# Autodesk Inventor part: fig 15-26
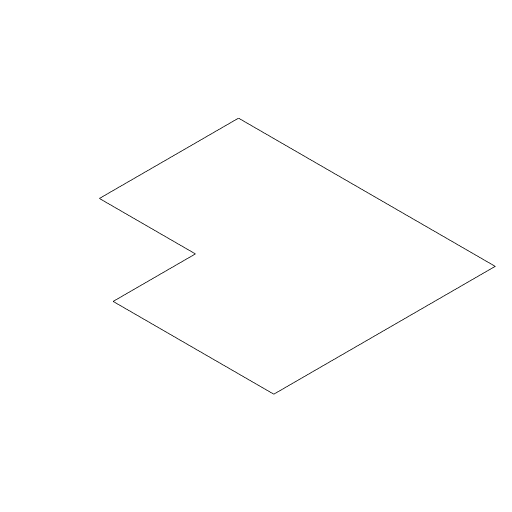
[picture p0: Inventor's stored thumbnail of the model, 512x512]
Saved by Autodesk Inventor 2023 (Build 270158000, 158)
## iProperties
Created: 2005-03
Part Number: fig 15-26
Document SubType Name: Sheet Metal
Designer: CADCIM
Manufacturer: Standard
Standards Organization: Custom
Density: 1 g/cm^3
Sheet Metal Rule: Default
Material: Generic
Appearance: Default
Author: CADCIM
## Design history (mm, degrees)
sketch "Sketch1"
  geometry: L1 (29.25, 32.25)-(-19.875, 32.25); L2 (-19.875, 32.25)-(-19.875, 5.625); L3 (-19.875, 5.625)-(-1.5, 5.625); L4 (-1.5, 5.625)-(-1.5, -10.125); L5 (-1.5, -10.125)-(29.25, -10.125); L6 (29.25, -10.125)-(29.25, 32.25)
  constraints: 12 end point, 4 parallel, 1 horizontal, 1 perpendicular
body "Solid1"
other parameters: "Thickness" = 0.5, "BendRadius" = 0.5 (= Thickness), "BendReliefWidth" = 0.5 (= Thickness), "BendReliefDepth" = 0.25 (= 0.5 x Thickness), "CornerReliefSize" = 2 (= 4 x Thickness), "SeamGap" = 0.01, "MinimumRemnant" = 1 (= 2 x Thickness), "TransitionRadius" = 0.5 (= BendRadius), "JacobiRadiusSize" = 0.5 (= Thickness), "GapSize" = 0.5 (= Thickness), "d0" = 0.5 (= BendRadius)
